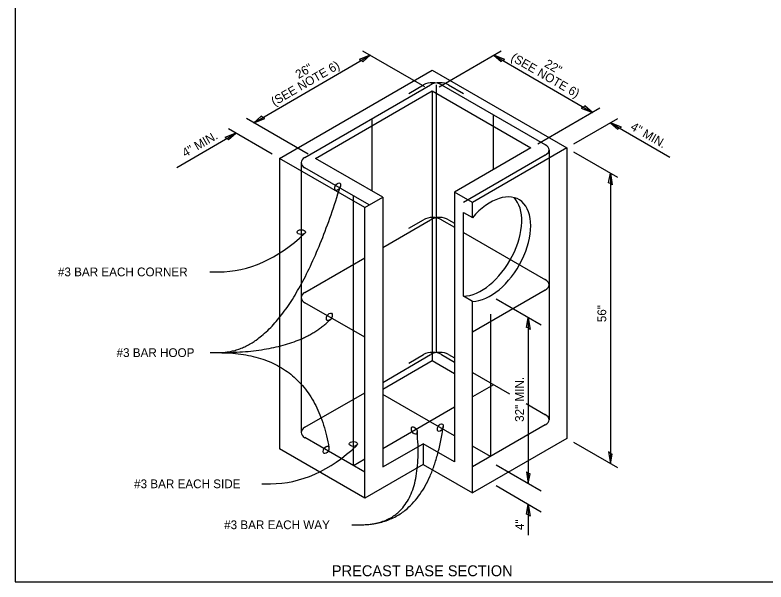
# Model space of a CAD drawing. Extents: x 99862 to 103151, y 100000 to 102076.
# Drawn here: x 99862 to 101238, y 100000 to 101038 of the extents above; entities that cross this region are included whole.
import ezdxf

# ---------------------------------------------------------------- set-up
doc = ezdxf.new("R2010")
doc.units = 0
for name, color, linetype in [('Level 1', 7, 'Continuous'), ('Level 10', 7, 'Continuous'), ('Level 11', 7, 'Continuous'), ('Level 15', 7, 'Continuous'), ('Level 20', 7, 'Continuous'), ('Level 44', 7, 'Continuous'), ('Level 60', 7, 'Continuous'), ('Level 8', 7, 'Continuous')]:
    doc.layers.add(name, color=color, linetype=linetype)

msp = doc.modelspace()

# ---------------------------------------------------------------- linework, layer by layer
at = {"layer": 'Level 1'}
msp.add_lwpolyline([(99862, 99999.5), (103151, 99999.5), (103151, 102075.5), (99862, 102075.5)], close=True, dxfattribs=at)
at = {"layer": 'Level 10'}
for p, q in [((100393.3, 100776.7), (100623.7, 100909.7)), ((100583.7, 100894.1), (100610.8, 100909.7)), ((100633.7, 100909.9), (100633.7, 100420.8)), ((100643.7, 100909.7), (100643.7, 100909.7)), ((100643.7, 100909.7), (100834.4, 100799.6)), ((100656.7, 100909.7), (100683.7, 100894.1)), ((100739, 100754.8), (100739, 100854.7)), ((100516.7, 100714.9), (100516.7, 100847.9)), ((100834.4, 100799.6), (100833.8, 100800)), ((100833.8, 100781), (100683.8, 100694.4)), ((100840.6, 100790.5), (100840.6, 100296.5)), ((100386.5, 100767.2), (100386.5, 100273.2)), ((100393.3, 100776.7), (100393.3, 100776.7)), ((100511.1, 100689.7), (100393.3, 100757.7)), ((100393.3, 100757.7), (100393.3, 100757.7)), ((100482.1, 100212.4), (100482.1, 100706.4)), ((100535.8, 100612), (100623.7, 100662.8)), ((100583.7, 100647.1), (100610.8, 100662.8)), ((100643.7, 100662.8), (100643.7, 100662.8)), ((100643.7, 100662.8), (100667.4, 100649.1)), ((100656.7, 100662.8), (100667.4, 100656.6)), ((100683.8, 100639.6), (100834.4, 100552.7)), ((100393.3, 100529.7), (100502.9, 100593)), ((100834.4, 100552.7), (100833.8, 100553)), ((100833.8, 100534), (100700.3, 100456.9)), ((100393.3, 100529.7), (100393.3, 100529.7)), ((100502.9, 100447.4), (100393.3, 100510.7)), ((100733.2, 100490), (100733.2, 100229)), ((100535.8, 100365), (100623.7, 100415.8)), ((100583.7, 100400.2), (100610.8, 100415.8)), ((100643.7, 100415.8), (100643.7, 100415.8)), ((100643.7, 100415.8), (100667.4, 100402.1)), ((100656.7, 100415.8), (100667.4, 100409.6)), ((100700.3, 100383.1), (100767.9, 100344)), ((100739, 100360.7), (100700.3, 100338.4)), ((100393.3, 100282.7), (100502.9, 100346)), ((100667.4, 100267), (100535.8, 100343)), ((100798.6, 100326.3), (100834.4, 100305.7)), ((100667.4, 100319.4), (100535.8, 100243.4)), ((100834.4, 100305.7), (100833.8, 100306)), ((100833.8, 100287), (100700.3, 100210)), ((100393.3, 100282.7), (100393.3, 100282.7)), ((100502.9, 100200.5), (100393.3, 100263.7)), ((100733.2, 100229), (100700.3, 100248)), ((100502.9, 100224.4), (100482.1, 100212.4))]:
    msp.add_line(p, q, dxfattribs=at)
for centre, major_axis, start_param, end_param in [((100627.2, 100900.2), (-23.3, 0), 3.926991, 5.497787), ((100640.2, 100900.2), (-23.3, 0), 3.926991, 5.497787), ((100817.3, 100790.5), (23.3, 0), 5.497787, 7.068583), ((100409.7, 100767.2), (-23.3, 0), 5.497787, 7.068583), ((100627.2, 100653.3), (-23.3, 0), 3.926991, 5.497787), ((100640.2, 100653.3), (-23.3, 0), 3.926991, 5.497787), ((100817.3, 100543.5), (23.3, 0), 5.497787, 7.068583), ((100409.7, 100520.2), (-23.3, 0), 5.497787, 7.068583), ((100627.2, 100406.3), (-23.3, 0), 3.926991, 5.497787), ((100640.2, 100406.3), (-23.3, 0), 3.926991, 5.497787), ((100817.3, 100296.5), (23.3, 0), 5.497787, 7.068583), ((100409.7, 100273.2), (-23.3, 0), 5.497787, 7.068583)]:
    msp.add_ellipse(centre, major_axis=major_axis, ratio=0.57735, start_param=start_param, end_param=end_param, dxfattribs=at)
at = {"layer": 'Level 11'}
for p, q in [((100346.6, 100775.1), (100626.2, 100936.6)), ((100626.2, 100936.6), (100873, 100794.1)), ((100412.4, 100775.1), (100626.2, 100898.6)), ((100626.2, 100898.6), (100626.2, 100404.7)), ((100626.2, 100898.6), (100807.2, 100794.1)), ((100807.2, 100794.1), (100667.4, 100713.4)), ((100873, 100794.1), (100700.3, 100694.4)), ((100873, 100794.1), (100873, 100262.2)), ((100346.6, 100775.1), (100346.6, 100243.2)), ((100502.9, 100684.9), (100346.6, 100775.1)), ((100535.8, 100703.9), (100412.4, 100775.1)), ((100785.5, 100699.6), (100785.5, 100699.6)), ((100535.8, 100352.4), (100626.2, 100404.7)), ((100626.2, 100404.7), (100667.4, 100380.9)), ((100873, 100262.2), (100700.3, 100162.5)), ((100502.9, 100153), (100346.6, 100243.2))]:
    msp.add_line(p, q, dxfattribs=at)
for points in [[(100802.4, 100483.4), (100805.8, 100461.8), (100802.4, 100464.7), (100799.1, 100465.7)], [(100802.4, 100179.5), (100805.8, 100197.2), (100802.4, 100198.2), (100799.1, 100201.1)], [(100802.4, 100141.5), (100805.8, 100119.9), (100802.4, 100122.7), (100799.1, 100123.8)]]:
    msp.add_lwpolyline(points, close=True, dxfattribs=at)
for centre, major_axis, start_param, end_param in [((100733.2, 100608.9), (-52.3, -90.7), 0.324844, 4.387545), ((100716.7, 100618.4), (52.3, 90.7), 3.466437, 6.125397)]:
    msp.add_ellipse(centre, major_axis=major_axis, ratio=0.57735, start_param=start_param, end_param=end_param, dxfattribs=at)
at = {"layer": 'Level 15'}
for p, q in [((100299.6, 100840.4), (100513.1, 100963.8)), ((100613.3, 100906.1), (100499.4, 100971.6)), ((100639.4, 100906.1), (100752.9, 100971.9)), ((100739.2, 100963.9), (100920.1, 100859.3)), ((100820.2, 100801.6), (100933.9, 100867.3)), ((100399.4, 100782.7), (100286.5, 100847.8)), ((100886, 100801.6), (100966.8, 100848.1)), ((100953, 100840.2), (101062, 100777.2)), ((100333.4, 100782.6), (100253, 100829.2)), ((100158.3, 100758.6), (100266.7, 100821.3)), ((100966.9, 100739.9), (100886, 100786.6)), ((100953, 100747.9), (100953, 100216)), ((100218.8, 100567.2), (100234.8, 100567.2)), ((100826.5, 100469.6), (100743.6, 100517.5)), ((100802.4, 100483.4), (100802.4, 100179.5)), ((100219.5, 100419.4), (100235.5, 100419.4)), ((100966.6, 100208.2), (100886, 100254.6)), ((100826.5, 100165.6), (100743.6, 100213.5)), ((100314.4, 100179.2), (100330.4, 100179.2)), ((100826.5, 100127.6), (100743.6, 100175.5)), ((100802.4, 100141.5), (100802.4, 100085.1)), ((100479, 100104.2), (100495, 100104.2))]:
    msp.add_line(p, q, dxfattribs=at)
for centre, major_axis in [((100453.2, 100723.1), (3.8, 6.58)), ((100386.5, 100640.1), (-7.6, 0)), ((100438, 100484.9), (3.8, 6.58)), ((100641.4, 100282), (3.8, 6.58)), ((100593.7, 100276.8), (-3.8, 6.58)), ((100432, 100241.4), (3.8, 6.58)), ((100482.1, 100252.2), (-7.6, 0))]:
    msp.add_ellipse(centre, major_axis=major_axis, ratio=0.57735, dxfattribs=at)
for centre in [(100234.8, 101171.2), (100330.4, 100783.2)]:
    msp.add_ellipse(centre, major_axis=(0, -604), ratio=0.557991, start_param=6.283185, end_param=6.770353, dxfattribs=at)
for points in [[(100235.5, 100419.4), (100364.5, 100419.4), (100458.1, 100723.4)], [(100235.5, 100419.4), (100380.5, 100419.4), (100440, 100480.3)], [(100235.5, 100419.4), (100407.4, 100419.4), (100437.3, 100245.5)], [(100495, 100104.2), (100620.7, 100104.2), (100646.7, 100283.9)], [(100495, 100104.2), (100614.4, 100104.2), (100599, 100274.5)]]:
    msp.add_open_spline(points, degree=2, dxfattribs=at)
at = {"layer": 'Level 44'}
for points in [[(100667.4, 100219.5), (100609.8, 100252.7), (100609.8, 100214.7), (100700.3, 100162.5), (100700.3, 100513.3), (100683.8, 100522.8), (100683.8, 100676), (100700.3, 100666.5), (100700.3, 100694.4), (100667.4, 100713.4)], [(100535.8, 100210), (100609.8, 100252.7), (100609.8, 100214.7), (100502.9, 100153), (100502.9, 100684.9), (100535.8, 100703.9)]]:
    msp.add_lwpolyline(points, close=True, dxfattribs=at)
at = {"layer": 'Level 60'}
msp.add_line((99862, 99999.5), (99862, 99999.5), dxfattribs=at)
at = {"layer": 'Level 8'}
for points in [[(100513.1, 100963.8), (100492.8, 100955.8), (100496.9, 100954.4), (100499.4, 100952)], [(100739.2, 100963.9), (100752.9, 100952.2), (100755.4, 100954.6), (100759.5, 100956)], [(100920.1, 100859.3), (100906.4, 100871), (100903.9, 100868.6), (100899.8, 100867.2)], [(100299.6, 100840.4), (100320, 100848.3), (100315.9, 100849.7), (100313.3, 100852.1)], [(100953, 100840.2), (100966.7, 100828.5), (100969.3, 100830.8), (100973.4, 100832.3)], [(100266.7, 100821.3), (100246.3, 100813.4), (100250.4, 100811.9), (100253, 100809.5)], [(100953, 100747.9), (100956.4, 100726.4), (100953, 100729.2), (100949.7, 100730.2)], [(100953, 100216), (100956.4, 100233.7), (100953, 100234.8), (100949.7, 100237.6)]]:
    msp.add_lwpolyline(points, close=True, dxfattribs=at)

# ---------------------------------------------------------------- texts
at = {"layer": 'Level 20'}
for s, rotation, p in [('(SEE NOTE 6)', 330.0271, (100769.2, 100955.3)), ('(SEE NOTE 6)', 29.9987, (100337.2, 100870.5)), ('26"', 29.9987, (100381.6, 100920.2)), ('  22"', 330.0271, (100820.7, 100949.7)), ('4" MIN.', 330.0271, (100988.5, 100828.5)), ('4" MIN.', 29.9987, (100174.1, 100776.7)), ('56"', 90.0001, (100945.4, 100475.1)), ('32" MIN.', 90.0001, (100794.5, 100292.6)), ('4"', 90.0001, (100794.8, 100094.5))]:
    msp.add_text(s, height=16, rotation=rotation, dxfattribs=at).set_placement(p)
for s, height, p in [('#3 BAR EACH CORNER', 16, (99940.6, 100559.2)), ('#3 BAR HOOP', 16, (100048.1, 100411.4)), ('#3 BAR EACH SIDE', 16, (100080.2, 100171.2)), ('#3 BAR EACH WAY', 16, (100245.2, 100096.2)), ('PRECAST BASE SECTION', 20, (100442.6, 100010))]:
    msp.add_text(s, height=height, dxfattribs=at).set_placement(p)

doc.saveas('drawing.dxf')
